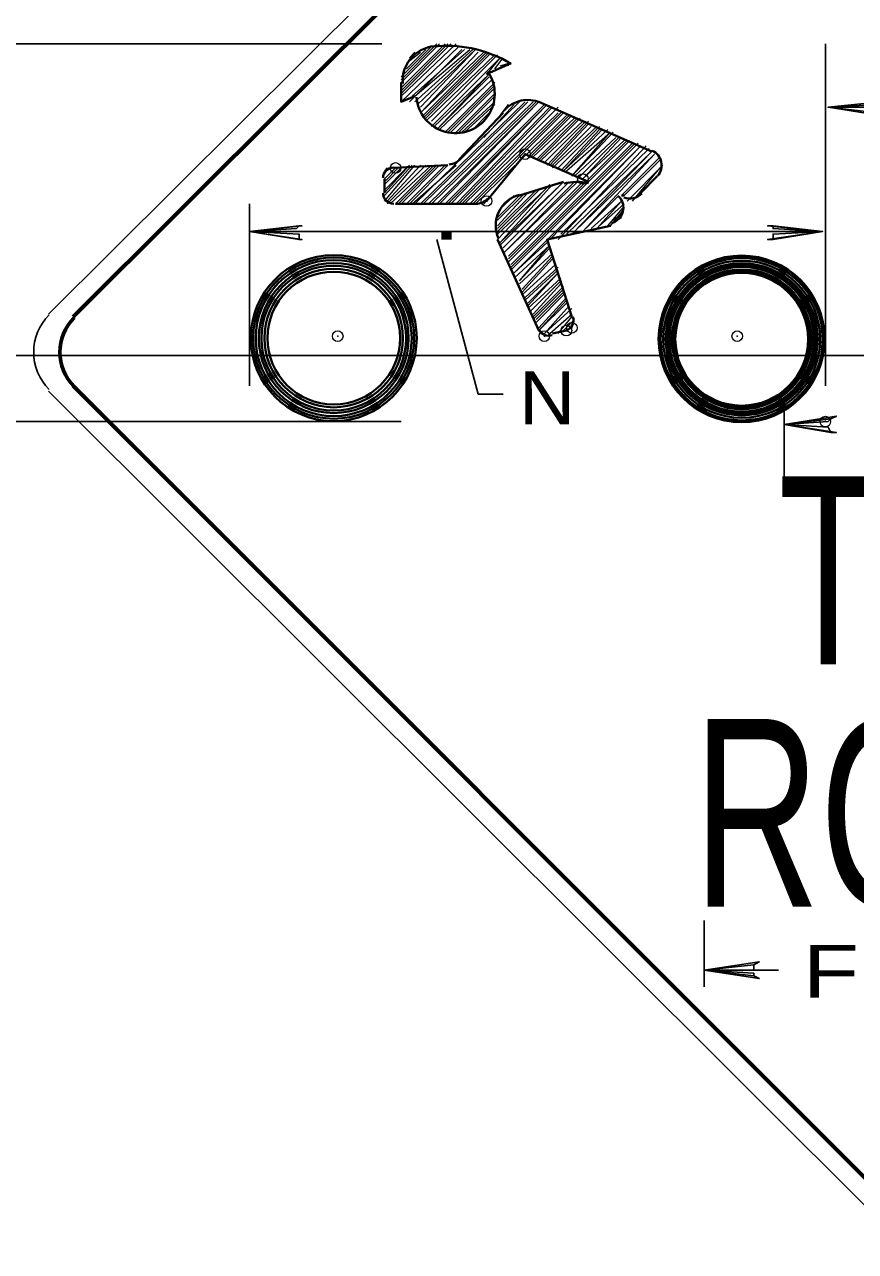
# Model space of a CAD drawing. Extents: x -0.018 to 0.195, y -0.006 to 0.263.
# Drawn here: x 0.0462 to 0.0839, y 0.1098 to 0.1654 of the extents above; entities that cross this region are included whole.
import ezdxf
from ezdxf.enums import TextEntityAlignment as Align

# ---------------------------------------------------------------- set-up
doc = ezdxf.new("R2010")
doc.units = 0
doc.header["$LTSCALE"] = 0.00096
doc.header["$PDMODE"] = 32
doc.header["$PDSIZE"] = 0.00048
doc.linetypes.add('DOT_DASHED', pattern=[7.7, 5, -1.2, 0.3, -1.2])
doc.layers.add('1', color=7, linetype='Continuous', lineweight=25)
doc.layers.add('12', color=7, linetype='Continuous', lineweight=13)

msp = doc.modelspace()

# ---------------------------------------------------------------- linework, layer by layer
at = {"layer": '1'}
for p, q in [((0.043625, 0.1645), (0.062375, 0.1645)), ((0.056375, 0.149), (0.056375, 0.15725)), ((0.056375, 0.156), (0.082375, 0.156)), ((0.02575, 0.147375), (0.06325, 0.147375))]:
    msp.add_line(p, q, dxfattribs=at)
at = {"layer": '1', "linetype": 'DOT_DASHED'}
msp.add_line((0.032375, 0.150375), (0.143125, 0.150375), dxfattribs=at)
at = {"layer": '1'}
msp.add_lwpolyline([(0.058625, 0.155625), (0.058625, 0.155875), (0.056375, 0.156), (0.058625, 0.155625), (0.05875, 0.155625), (0.056375, 0.156), (0.0585, 0.156125), (0.058625, 0.15625), (0.056375, 0.156), (0.05875, 0.15625), (0.058625, 0.15625)], dxfattribs=at)
at = {"layer": '12', "lineweight": 25}
for p, q in [((0.04725, 0.15225), (0.086375, 0.191125)), ((0.063625, 0.163875), (0.063875, 0.164125)), ((0.0825, 0.149), (0.0825, 0.1645)), ((0.068125, 0.163625), (0.06825, 0.163625)), ((0.06775, 0.16125), (0.068125, 0.16175)), ((0.082625, 0.161625), (0.088375, 0.161625)), ((0.072875, 0.1565), (0.07325, 0.15675)), ((0.072875, 0.1565), (0.07325, 0.15675)), ((0.073, 0.1565), (0.07325, 0.156625)), ((0.06675, 0.148625), (0.064875, 0.155625)), ((0.086375, 0.10975), (0.04725, 0.14875)), ((0.06675, 0.148625), (0.067875, 0.148625)), ((0.080625, 0.144875), (0.080625, 0.148)), ((0.077, 0.12175), (0.077, 0.12475)), ((0.077, 0.1225), (0.080375, 0.1225))]:
    msp.add_line(p, q, dxfattribs=at)
at = {"layer": '12', "lineweight": 60}
for p, q in [((0.048375, 0.152125), (0.0865, 0.190125)), ((0.0865, 0.110875), (0.048375, 0.149))]:
    msp.add_line(p, q, dxfattribs=at)
at = {"layer": '12'}
for p, q in [((0.06325, 0.162875), (0.064875, 0.1645)), ((0.06325, 0.16275), (0.065, 0.1645)), ((0.06325, 0.1625), (0.06525, 0.1645)), ((0.06325, 0.162375), (0.065375, 0.1645)), ((0.06325, 0.16225), (0.0655, 0.1645)), ((0.06325, 0.162125), (0.06575, 0.1645)), ((0.06325, 0.163), (0.064625, 0.164375)), ((0.06325, 0.161875), (0.065875, 0.164375)), ((0.0635, 0.163375), (0.064375, 0.16425)), ((0.0635, 0.163625), (0.064125, 0.164125)), ((0.063625, 0.161875), (0.066, 0.16425)), ((0.06375, 0.162125), (0.066125, 0.16425)), ((0.063875, 0.162125), (0.066375, 0.16425)), ((0.063875, 0.161875), (0.0665, 0.16425)), ((0.064, 0.16175), (0.066625, 0.16425)), ((0.064125, 0.161625), (0.066625, 0.16425)), ((0.064125, 0.161375), (0.06675, 0.164125)), ((0.064125, 0.161375), (0.067, 0.164125)), ((0.06425, 0.16125), (0.067125, 0.164125)), ((0.06425, 0.161125), (0.06725, 0.164125)), ((0.064375, 0.161125), (0.06725, 0.164)), ((0.064375, 0.161), (0.0675, 0.164)), ((0.064625, 0.161), (0.067625, 0.164)), ((0.064625, 0.16075), (0.06775, 0.163875)), ((0.06725, 0.16325), (0.06775, 0.163875)), ((0.0675, 0.163375), (0.067875, 0.163875)), ((0.06775, 0.1635), (0.068125, 0.163625)), ((0.068125, 0.1635), (0.068125, 0.163625)), ((0.06475, 0.16075), (0.06725, 0.163125)), ((0.064875, 0.160625), (0.06725, 0.163125)), ((0.064875, 0.160625), (0.06725, 0.163)), ((0.065, 0.160625), (0.067375, 0.162875)), ((0.06525, 0.1605), (0.0675, 0.16275)), ((0.065375, 0.1605), (0.0675, 0.162625)), ((0.0655, 0.1605), (0.0675, 0.1625)), ((0.063875, 0.15725), (0.068625, 0.161875)), ((0.064125, 0.15725), (0.068875, 0.161875)), ((0.06425, 0.15725), (0.069, 0.161875)), ((0.0645, 0.15725), (0.06925, 0.161875)), ((0.064625, 0.15725), (0.069375, 0.161875)), ((0.064875, 0.15725), (0.0695, 0.161875)), ((0.065, 0.15725), (0.0695, 0.161875)), ((0.06575, 0.1605), (0.0675, 0.16225)), ((0.065875, 0.1605), (0.0675, 0.162125)), ((0.066, 0.1605), (0.0675, 0.161875)), ((0.06525, 0.15725), (0.06975, 0.16175)), ((0.065375, 0.15725), (0.069875, 0.16175)), ((0.0655, 0.15725), (0.069875, 0.16175)), ((0.06575, 0.15725), (0.07, 0.161625)), ((0.065875, 0.15725), (0.070125, 0.161625)), ((0.066, 0.15725), (0.070375, 0.161625)), ((0.066125, 0.1605), (0.0675, 0.16175)), ((0.066125, 0.15725), (0.070375, 0.161375)), ((0.066375, 0.15725), (0.0705, 0.161375)), ((0.0665, 0.160625), (0.06725, 0.161375)), ((0.0665, 0.15725), (0.070625, 0.161375)), ((0.067, 0.16025), (0.068375, 0.16175)), ((0.066625, 0.15725), (0.07075, 0.16125)), ((0.069, 0.159375), (0.070875, 0.16125)), ((0.069125, 0.159375), (0.071, 0.16125)), ((0.06925, 0.159375), (0.071125, 0.161125)), ((0.069375, 0.15925), (0.07125, 0.161125)), ((0.0695, 0.15925), (0.071375, 0.161125)), ((0.069625, 0.15925), (0.0715, 0.161)), ((0.06975, 0.159125), (0.071625, 0.161)), ((0.069875, 0.159), (0.07175, 0.161)), ((0.07, 0.159), (0.07175, 0.160875)), ((0.070125, 0.159), (0.071875, 0.16075)), ((0.070125, 0.158875), (0.072125, 0.16075)), ((0.070375, 0.158875), (0.07225, 0.16075)), ((0.0705, 0.15875), (0.07225, 0.160625)), ((0.070625, 0.15875), (0.072375, 0.160625)), ((0.070625, 0.15875), (0.072625, 0.160625)), ((0.07075, 0.15875), (0.07275, 0.1605)), ((0.071, 0.1585), (0.07275, 0.1605)), ((0.071, 0.1585), (0.072875, 0.1605)), ((0.071125, 0.1585), (0.073, 0.16025)), ((0.07125, 0.158375), (0.073125, 0.16025)), ((0.0715, 0.158375), (0.07325, 0.16025)), ((0.06825, 0.1545), (0.07375, 0.16)), ((0.06825, 0.154375), (0.073875, 0.16)), ((0.06825, 0.15425), (0.074, 0.16)), ((0.068375, 0.154125), (0.074125, 0.159875)), ((0.07, 0.155625), (0.074125, 0.159875)), ((0.070375, 0.155625), (0.074375, 0.159875)), ((0.0705, 0.155875), (0.0745, 0.15975)), ((0.0715, 0.158375), (0.073375, 0.160125)), ((0.07075, 0.155875), (0.074625, 0.159625)), ((0.071, 0.155875), (0.074625, 0.159625)), ((0.071125, 0.156), (0.07475, 0.1595)), ((0.0715, 0.156), (0.07475, 0.1595)), ((0.07325, 0.157625), (0.075, 0.159375)), ((0.07325, 0.157625), (0.075, 0.159375)), ((0.073375, 0.157625), (0.075, 0.15925)), ((0.0625, 0.15775), (0.063625, 0.159)), ((0.0625, 0.157625), (0.06375, 0.159)), ((0.0625, 0.157375), (0.063875, 0.159)), ((0.0625, 0.15875), (0.062625, 0.158875)), ((0.0625, 0.158375), (0.063, 0.158875)), ((0.0625, 0.15825), (0.063125, 0.158875)), ((0.0625, 0.158125), (0.06325, 0.158875)), ((0.0625, 0.157875), (0.0635, 0.158875)), ((0.062625, 0.157375), (0.064125, 0.159)), ((0.062625, 0.15725), (0.064375, 0.159)), ((0.06275, 0.15725), (0.064625, 0.159)), ((0.063, 0.15725), (0.06475, 0.159)), ((0.063125, 0.15725), (0.064875, 0.159)), ((0.06325, 0.15725), (0.065, 0.159)), ((0.0635, 0.15725), (0.06525, 0.159)), ((0.063625, 0.15725), (0.065375, 0.159)), ((0.06375, 0.15725), (0.06575, 0.159)), ((0.0735, 0.157375), (0.075125, 0.159)), ((0.07375, 0.157375), (0.075, 0.158875)), ((0.067, 0.15725), (0.067875, 0.15825)), ((0.067625, 0.155625), (0.07, 0.158125)), ((0.06775, 0.155375), (0.070625, 0.15825)), ((0.06775, 0.1555), (0.070125, 0.158125)), ((0.06775, 0.1555), (0.0705, 0.158125)), ((0.067875, 0.15525), (0.070875, 0.15825)), ((0.067875, 0.155), (0.071125, 0.15825)), ((0.067875, 0.155), (0.07125, 0.15825)), ((0.068125, 0.154875), (0.0715, 0.15825)), ((0.074, 0.157625), (0.074625, 0.15825)), ((0.067625, 0.156125), (0.069375, 0.157875)), ((0.067625, 0.156), (0.0695, 0.157875)), ((0.067625, 0.155875), (0.06975, 0.157875)), ((0.067625, 0.1565), (0.068875, 0.15775)), ((0.067625, 0.15625), (0.069, 0.15775)), ((0.067625, 0.156625), (0.068625, 0.157625)), ((0.06775, 0.157), (0.068375, 0.157625)), ((0.071625, 0.156125), (0.073125, 0.157625)), ((0.071875, 0.156125), (0.07325, 0.157375)), ((0.072125, 0.156125), (0.07325, 0.157375)), ((0.07225, 0.15625), (0.073375, 0.15725)), ((0.072625, 0.15625), (0.073375, 0.157125)), ((0.07275, 0.15625), (0.073375, 0.157)), ((0.068375, 0.154125), (0.069875, 0.1555)), ((0.068375, 0.153875), (0.07, 0.155375)), ((0.068625, 0.15375), (0.07, 0.155375)), ((0.068625, 0.15375), (0.07, 0.15525)), ((0.068625, 0.153625), (0.070125, 0.155)), ((0.06875, 0.153375), (0.070125, 0.154875)), ((0.06875, 0.15325), (0.070125, 0.15475)), ((0.06875, 0.15325), (0.070125, 0.15475)), ((0.06875, 0.153125), (0.07025, 0.1545)), ((0.068875, 0.153), (0.070375, 0.154375)), ((0.068875, 0.152875), (0.070375, 0.15425)), ((0.069, 0.15275), (0.070375, 0.154125)), ((0.069, 0.152625), (0.070375, 0.154125)), ((0.069, 0.1525), (0.0705, 0.153875)), ((0.069125, 0.152375), (0.0705, 0.15375)), ((0.06925, 0.15225), (0.0705, 0.153625)), ((0.06925, 0.152125), (0.070625, 0.1535)), ((0.06925, 0.152), (0.070625, 0.153375)), ((0.069375, 0.152), (0.070625, 0.15325)), ((0.069375, 0.151875), (0.070625, 0.153125)), ((0.0695, 0.151625), (0.07075, 0.153)), ((0.0695, 0.1515), (0.07075, 0.152875)), ((0.0695, 0.1515), (0.07075, 0.15275)), ((0.06975, 0.151375), (0.070875, 0.152625)), ((0.06975, 0.151375), (0.071, 0.1525)), ((0.069875, 0.15125), (0.071, 0.15225)), ((0.07, 0.151375), (0.071, 0.15225)), ((0.070375, 0.151375), (0.071, 0.152125)), ((0.070625, 0.1515), (0.071125, 0.152)), ((0.07075, 0.1515), (0.071, 0.151625))]:
    msp.add_line(p, q, dxfattribs=at)
at = {"layer": '12', "lineweight": 40}
for p, q in [((0.06825, 0.163625), (0.067125, 0.163125)), ((0.0695, 0.161875), (0.074625, 0.159625)), ((0.065875, 0.15925), (0.067875, 0.161375)), ((0.062875, 0.158875), (0.065375, 0.159)), ((0.0625, 0.15775), (0.0625, 0.158375)), ((0.068625, 0.157625), (0.070625, 0.15825)), ((0.074875, 0.1585), (0.074125, 0.15775)), ((0.073375, 0.157625), (0.07325, 0.157625)), ((0.066625, 0.15725), (0.063, 0.15725)), ((0.0695, 0.1515), (0.067625, 0.155625)), ((0.07075, 0.1515), (0.070125, 0.151375))]:
    msp.add_line(p, q, dxfattribs=at)
for points in [[(0.063875, 0.162125), (0.06325, 0.161875), (0.06325, 0.16275)], [(0.07175, 0.15825), (0.068875, 0.1595), (0.067125, 0.157375)], [(0.07275, 0.15625), (0.069875, 0.155625), (0.071, 0.152125)]]:
    msp.add_lwpolyline(points, dxfattribs=at)
at = {"layer": '12', "lineweight": 25}
for points in [[(0.085, 0.16125), (0.084875, 0.161375), (0.082625, 0.161625), (0.085, 0.16125), (0.085, 0.16125), (0.082625, 0.161625), (0.084875, 0.16175), (0.085, 0.161875), (0.082625, 0.161625), (0.085, 0.161875), (0.085, 0.161875)], [(0.080125, 0.15625), (0.080125, 0.156125), (0.082375, 0.156), (0.080125, 0.15625), (0.079875, 0.15625), (0.082375, 0.156), (0.080125, 0.155875), (0.080125, 0.155625), (0.082375, 0.156), (0.079875, 0.155625), (0.080125, 0.155625)], [(0.08275, 0.146875), (0.082625, 0.147125), (0.080625, 0.14725), (0.08275, 0.146875), (0.083, 0.146875), (0.080625, 0.14725), (0.082625, 0.147375), (0.08275, 0.1475), (0.080625, 0.14725), (0.083, 0.147625), (0.08275, 0.1475)], [(0.07925, 0.12225), (0.07925, 0.122375), (0.077, 0.1225), (0.07925, 0.12225), (0.0795, 0.122125), (0.077, 0.1225), (0.07925, 0.1225), (0.07925, 0.12275), (0.077, 0.1225), (0.0795, 0.122875), (0.07925, 0.12275)]]:
    msp.add_lwpolyline(points, dxfattribs=at)
at = {"layer": '12'}
for points in [[(0.068125, 0.15475), (0.071625, 0.15825), (0.0735, 0.160125)], [(0.068125, 0.154625), (0.07175, 0.15825), (0.073625, 0.160125)]]:
    msp.add_lwpolyline(points, dxfattribs=at)
at = {"layer": '12', "lineweight": 40}
for centre, radius in [((0.0601939, 0.1511609), 0.00376595), ((0.0601938, 0.1511609), 0.00365366), ((0.0601938, 0.1511609), 0.0035395), ((0.0787023, 0.1511341), 0.00376595), ((0.0787027, 0.1511069), 0.00376309), ((0.0787027, 0.1511069), 0.0036771), ((0.0787027, 0.1511069), 0.00356197), ((0.0601938, 0.1511609), 0.0033981), ((0.0601938, 0.1511609), 0.00328248), ((0.0601938, 0.1511609), 0.00314002), ((0.0601938, 0.1511609), 0.00301007), ((0.0787027, 0.1511069), 0.00344883), ((0.0787027, 0.1511069), 0.00336407), ((0.0787027, 0.1511069), 0.00327931), ((0.0787027, 0.1511069), 0.0031649), ((0.0787027, 0.1511069), 0.00307945), ((0.0787027, 0.1511069), 0.00301007)]:
    msp.add_circle(centre, radius, dxfattribs=at)
for centre, radius, start, end in [((0.0648927, 0.1628315), 0.00157073, 88.48155, 184.50302), ((0.0653023, 0.1586821), 0.00573138, 59.34443, 93.68044), ((0.065719, 0.1622308), 0.00178062, 184.73358, 34.57944), ((0.0689987, 0.1605206), 0.00143991, 66.67194, 137.92055), ((0.0743524, 0.1589968), 0.00071996, 317.92507, 66.67235), ((0.0653975, 0.159755), 0.00071996, 273.06876, 317.92113), ((0.0629149, 0.1584201), 0.00047997, 93.07155, 180), ((0.0712299, 0.1558425), 0.00239985, 77.2352, 104.29543), ((0.0629149, 0.1577305), 0.00047997, 180, 270), ((0.0666465, 0.1579705), 0.00071996, 270, 318.15714), ((0.0689851, 0.1562613), 0.00143991, 104.30228, 204.0018), ((0.072617, 0.1570743), 0.00071996, 284.30085, 45.5135), ((0.0736359, 0.1582029), 0.00071996, 246.68699, 317.90094), ((0.0705935, 0.1519715), 0.00047997, 288.85434, 18.41684), ((0.0699433, 0.1517495), 0.00047997, 203.9931, 288.84203)]:
    msp.add_arc(centre, radius, start, end, dxfattribs=at)
at = {"layer": '12', "lineweight": 25}
msp.add_arc((0.0489811, 0.1505236), 0.00239953, 135, 225, dxfattribs=at)
at = {"layer": '12', "lineweight": 60}
msp.add_arc((0.0499709, 0.1505236), 0.00219957, 135, 225, dxfattribs=at)
at = {"layer": '12'}
for p in [(0.068875, 0.1595), (0.063, 0.158875), (0.0715, 0.158375), (0.067125, 0.157375), (0.071, 0.151625), (0.060375, 0.15125), (0.06975, 0.15125), (0.07075, 0.1515), (0.0785, 0.15125), (0.0825, 0.147375)]:
    msp.add_point(p, dxfattribs=at)

# ---------------------------------------------------------------- texts
for s, height, width, p in [('.', 0.002399, 1.55, (0.064625, 0.155625)), ('THE', 0.008517, 0.65, (0.080375, 0.136375)), ('ROAD', 0.008517, 0.7, (0.0765, 0.125375))]:
    msp.add_text(s, height=height, dxfattribs=dict(at, width=width)).set_placement(p)
for s, width, p in [('N', 1.1, (0.069875, 0.14725)), ('F', 1.3, (0.08275, 0.12125))]:
    msp.add_text(s, height=0.002399, dxfattribs=dict(at, width=width)).set_placement(p, align=Align.CENTER)

doc.saveas('drawing.dxf')
